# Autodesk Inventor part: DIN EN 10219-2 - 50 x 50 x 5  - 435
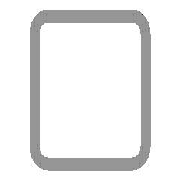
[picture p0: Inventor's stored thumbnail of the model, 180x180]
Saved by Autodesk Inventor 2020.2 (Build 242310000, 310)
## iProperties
Created: 2019-01
Part Number: DIN EN 10219-2 - 50 x 50 x 5  - 435
Material: Stahl, weich
Description: Kaltgeformte, geschweißte Baustahl-Hohlprofile aus unlegiertem Feinkorn-Baustahl
Document SubType Name: Modeling
Standard: DIN
Designer: lutzd
Standard Revision: 2006-07
Standards Organization: DIN
Language: de-DE
Size Designation: 50 x 50 x 5
Categories: <MemberInstance><Categories><Category DisplayName="Profile" InternalName="089c4875-fa83-4c05-b084-43b9cc11f5ed" Mnemonic="GRDR"><CategoryParameter DisplayName="
Stock Number: 50 x 50 x 5
Mass: 2853.43 g
Surface Area: 1470.69 cm^2
Volume: 363.494 cm^3
Density: 7.85 g/cm^3
Appearance: Semi-Polished(8)
IsCustomPart: 1
G_L: 435,000 mm
G_W: 50,000 mm
G_H: 50,000 mm
Mass: 2,853 kg
VLT_Material: Stahl, weich
DocNumber: ADSK-014379
Folder: .
+D1FB912F-87EA-4C42-960D-0160D2D9837C+SCHNITTDETAIL1: Schnittwinkel 90,00 grd
+A59AB96C-240B-4F06-8576-76846DDAD07E+SCHNITTDETAIL2: Schnittwinkel 90,00 grd
Dimensions: 50x50x435 mm
_CCFamilyMember: 16
_CCFamilyDisplayName: DIN EN 10219-2 (Quadratisches Hohlprofil - Kaltgeformt) - Kaltgeformte, geschweißte Baustahl-Hohlprofile aus unlegiertem Feinkorn-Baustahl
_FrameMemberDoc: Frame Member File
_Version: 15.0.0
_GetPNFromCC: 1
Title: Profil-Bauteil
Author: lutzd
Revision Number: -
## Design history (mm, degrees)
node "Startebene"
node "Endebene"
sketch "Skizze"
  geometry: L1 (-25, -15)-(-25, 15); L2 (-15, 25)-(15, 25); L3 (25, 15)-(25, -15); L4 (15, -25)-(-15, -25); L5 (-15, 20)-(15, 20); L6 (20, 15)-(20, -15); L7 (15, -20)-(-15, -20); L8 (-20, -15)-(-20, 15); L9 (0, 37.899)-(0, -37.899) reference; L10 (-37.899, 0)-(37.899, 0) reference; A1 r 10 centre (-15, -15) between (-25, -15) and (-15, -25); A2 r 10 centre (-15, 15) between (-15, 25) and (-25, 15); A3 r 10 centre (15, 15) between (25, 15) and (15, 25); A4 r 10 centre (15, -15) between (15, -25) and (25, -15); A5 r 5 centre (-15, 15) between (-15, 20) and (-20, 15); A6 r 5 centre (15, 15) between (20, 15) and (15, 20); A7 r 5 centre (15, -15) between (15, -20) and (20, -15); A8 r 5 centre (-15, -15) between (-20, -15) and (-15, -20)
  constraints: 16 end point, 16 point on circle, 8 centre point, 8 tangent, 4 parallel, 3 equal radius, 2 perpendicular, 7 other
  dimensions: "d7" = 10 radius of A1 (= G_IR); "d10" = 50 distance between parallel lines of L2 L4 (= G_H); "d11" = 50 distance between parallel lines of L1 L3 (= G_W); "d12" = 5 distance between parallel lines of L3 L6 (= G_T); "d15" = 25 distance between parallel lines of L2 L10 (= 0.5 x d10); "d16" = 25 distance between parallel lines of L9 L3 (= 0.5 x d11)
extrude "Körper" new body sketch "Skizze" stored distance "d3" = 435 (= G_L); taper "d4" = 0 deg
node "Driven Length"
  sketch "Sketch3"
    geometry: L1 (0, 0)-(10, 0) reference
    constraints: 2 end point, 1 horizontal
  workplane "Work Plane3"
  sketch "Sketch4"
    geometry: L1 (-2, 25)-(12, 25) reference; L2 (-2, 460)-(12, 460) reference
    dimensions: "d18" = 435 distance between parallel lines of L1 L2 (derived)
workplane "Arbeitsebene4"
feature "Trennen1"
workplane "Arbeitsebene5"
feature "Trennen2"
body "Solid1"
other parameters: "G_W" = 50 [user parameter; used in 1 equation term], "G_H" = 50 [user parameter; used in 1 equation term], "G_T" = 5 [user parameter; used in 1 equation term], "G_IR" = 10 [user parameter; used in 1 equation term], "G_L" = 435 (= d18) [user parameter; used in 1 equation term], "G_OFFSET_START" = -25 [user parameter; used in 1 equation term], "d13" = 25 (= -G_OFFSET_START), "d17" = 90 deg
